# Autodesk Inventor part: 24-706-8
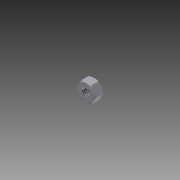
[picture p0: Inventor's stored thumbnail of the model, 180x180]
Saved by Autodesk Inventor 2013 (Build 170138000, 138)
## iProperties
Created: 2004-11
Part Number: 24-706-8
Material: Edelstahl, austenitisch
Description: Hexagon Nut, M8
Document SubType Name: Modeling
Designer: Autodesk, Inc.
Manufacturer: Standard
Standards Organization: Custom
Catalog Web Link: http://www.parker.com/ead/cm1.asp?cmid=809
Vendor: PARKER IPS
Mass: 6.05208 g
Surface Area: 6.5618 cm^2
Volume: 0.753683 cm^3
Density: 8.03 g/cm^3
CAGE: 1LJX3
Dept. ID: Product Design
Description #2: ---
Finish #1: ---
Finish #2: ---
Material ID: ---
Project Number: ---
Author: Autodesk, Inc.
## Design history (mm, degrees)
derived "24-7X6 Hexagon Nuts.ipt"
body "Solid1"
tag "TaggingFeature2"
feature "Solid1::24-7X6 Hexagon Nuts.ipt" dims "ScaleForDerivedMember" = 10
